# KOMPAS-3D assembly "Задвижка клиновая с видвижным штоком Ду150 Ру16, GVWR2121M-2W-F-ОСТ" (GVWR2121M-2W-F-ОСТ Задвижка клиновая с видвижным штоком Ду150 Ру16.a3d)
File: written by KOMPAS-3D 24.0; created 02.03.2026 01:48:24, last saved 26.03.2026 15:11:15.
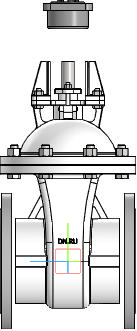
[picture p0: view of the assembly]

Document properties: Автор: R2D2; Полное имя файла: E:\Работа\Зайцев\GVWR2121M-2W-F-ОСТ Задвижка клиновая с видвижным штоком Ду50-300 Ру16\DN150\Исходные материалы\GVWR2121M-2W-F-ОСТ Задвижка клиновая с видвижным штоком Ду150 Ру16.a3d

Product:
- Component [detail]: ANSI B18.2.4.2M - M16x2 - 24  | designation ANSI B18.2.4.2M - M16x2  | qty 8  | pos. 2  | Масса: 0.044671; Комментарий: Типы метрических   шестигранных гаек   2; Автор: R2D2; additional columns: Сталь, мягкая; source file: ANSI B18.2.4.2M - M16x2 ANSI B18.2.4.2M - M16x2 - 24.m3d
- Component [detail]: AS 1110 - M16 x 60  | qty 8  | pos. 3  | Масса: 0.133772; Комментарий: Болты и винты   шестигранные точные   метрические ISO; Автор: R2D2; additional columns: Сталь, мягкая; source file: AS 1110 - M16 x 60 AS 1110 - M16 x 60.m3d
- Component [detail]: AS 1110 - M10 x 35  | qty 4  | pos. 4  | Масса: 0.032708; Комментарий: Болты и винты   шестигранные точные   метрические ISO; Автор: R2D2; additional columns: Сталь, мягкая; source file: AS 1110 - M10 x 35 AS 1110 - M10 x 35.m3d
- Component [detail]: ANSI B18.2.4.2M - M10x1,5 - 16  | designation ANSI B18.2.4.2M - M10x1,5  | qty 4  | pos. 5  | Масса: 0.012122; Комментарий: Типы метрических   шестигранных гаек   2; Автор: R2D2; additional columns: Сталь, мягкая; source file: ANSI B18.2.4.2M - M10x1,5 ANSI B18.2.4.2M - M10x1,5 - 16.m3d
- Component [detail]: ANSI B18.2.4.2M - M8x1,25 - 13  | designation ANSI B18.2.4.2M - M8x1,25  | qty 1  | pos. 6  | Масса: 0.006562; Комментарий: Типы метрических   шестигранных гаек   2; Автор: R2D2; additional columns: Сталь, мягкая; source file: ANSI B18.2.4.2M - M8x1,25 ANSI B18.2.4.2M - M8x1,25 - 13.m3d
- Component [detail]: Деталь1  | qty 1  | pos. 7  | Масса: 77.234324; Автор: R2D2; additional columns: Типовые; source file: 2.m3d
- Component [detail]: Фланец  | qty 1  | pos. 8  | Масса: 7.180576; Автор: R2D2; additional columns: Типовые; source file: Фланец DN150 PN16 b24.m3d
- Component [detail]: Фланец  | qty 1  | pos. 9  | Масса: 7.180576; Автор: R2D2; additional columns: Типовые; source file: Фланец DN150 PN16 b24.m3d
- Component [detail]: ANSI B18.2.4.2M - M8x1,25 - 13  | designation ANSI B18.2.4.2M - M8x1,25-01  | qty 1  | pos. 6  | Масса: 0.006562; Комментарий: Типы метрических   шестигранных гаек   2; Автор: R2D2; additional columns: Сталь, мягкая; source file: ANSI B18.2.4.2M - M8x1,25 ANSI B18.2.4.2M - M8x1,25 - 13.m3d
- Component [assembly]: DN50_3D_STEP  | designation Сборка  | qty 1  | Масса: 2.725126; Автор: R2D2; source file: Фланец А.a3d
- Part/product: Задвижка клиновая с видвижным штоком Ду150 Ру16  | designation GVWR2121M-2W-F-ОСТ
    Масса: 60
    Раздел спецификации: Прочие изделия
    Примечание: D040-10013
    additional columns: D040-10013

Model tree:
1. Массив по сетке:2  (labels: Грань.Твердое тело1; Вершина.Твердое тело1)  (4 pattern instances)
     Шаг 1 = 50; Угол раствора = 90; Шаг 2 = 120
2. Массив по концентрической сетке:1  (with: Грань.Элемент вращения:1, Грань.Операция без истории:2)  (labels: Грань.Твердое тело1; Грань.Solid1)  (8 pattern instances)
     Шаг 2 = 360; Расстояние = -140; Ориентация = 2; Ориентация = 2; Расстояние = -539

Referenced files in E:\Работа\Зайцев\GVWR2121M-2W-F-ОСТ Задвижка клиновая с видвижным штоком Ду50-300 Ру16\DN150\Исходные материалы\: ANSI B18.2.4.2M - M16x2 ANSI B18.2.4.2M - M16x2 - 24.m3d, AS 1110 - M16 x 60 AS 1110 - M16 x 60.m3d, AS 1110 - M10 x 35 AS 1110 - M10 x 35.m3d, ANSI B18.2.4.2M - M10x1,5 ANSI B18.2.4.2M - M10x1,5 - 16.m3d, ANSI B18.2.4.2M - M8x1,25 ANSI B18.2.4.2M - M8x1,25 - 13.m3d, 2.m3d, Фланец DN150 PN16 b24.m3d, Фланец А.a3d
Referenced files in E:\Работа\Зайцев\GVWR2626M-2W-F-S Задвижка клиновая с выдвижным штоком DN.ru Ду50-300 Ру16\DN150\исходные материалы\: Фланец DN150 PN16 b24.m3d
Referenced files in E:\Работа\Зайцев\GVWR3131M-2W-F-S Задвижка клиновая с выдвижным штоком DN.ru Ду50-200 Ру63\DN150\исходные материалы\: ANSI B18.2.4.2M - M10x1,5 ANSI B18.2.4.2M - M10x1,5 - 16.m3d, AS 1110 - M10 x 35 AS 1110 - M10 x 35.m3d, ANSI B18.2.4.2M - M16x2 ANSI B18.2.4.2M - M16x2 - 24.m3d, AS 1110 - M16 x 60 AS 1110 - M16 x 60.m3d
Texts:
  Программные изделия  и базы данных
  ANSI B18.2.4.2M - M16x2
  ANSI B18.2.4.2M - M10x1,5
  ANSI B18.2.4.2M - M8x1,25
  ANSI B18.2.4.2M - M8x1,25 - 01
  ANSI B18.2.4.2M - M8x1,25-01
  GVWR2121M-2W-F-ОСТ
  ANSI B18.2.4.2M - M16x2 ANSI B18.2.4.2M - M16x2 - 24 (1)
  AS 1110 - M16 x 60 AS 1110 - M16 x 60 (1)
  AS 1110 - M10 x 35 AS 1110 - M10 x 35 (1)
  ANSI B18.2.4.2M - M10x1,5 ANSI B18.2.4.2M - M10x1,5 - 16 (1)
  ANSI B18.2.4.2M - M8x1,25 ANSI B18.2.4.2M - M8x1,25 - 13
  Деталь1 Деталь1
  Фланец (1)
  Фланец (2)
  ANSI B18.2.4.2M - M8x1,25-01 ANSI B18.2.4.2M - M8x1,25 - 13
  Сборка DN50_3D_STEP
  Ось Z.Начало координат
  Ось Y.Начало координат
  Плоскость ZY.Начало координат
  Плоскость ZX.Начало координат
  Плоскость XY.Начало координат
